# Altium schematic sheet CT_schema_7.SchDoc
size 274 x 160 mm
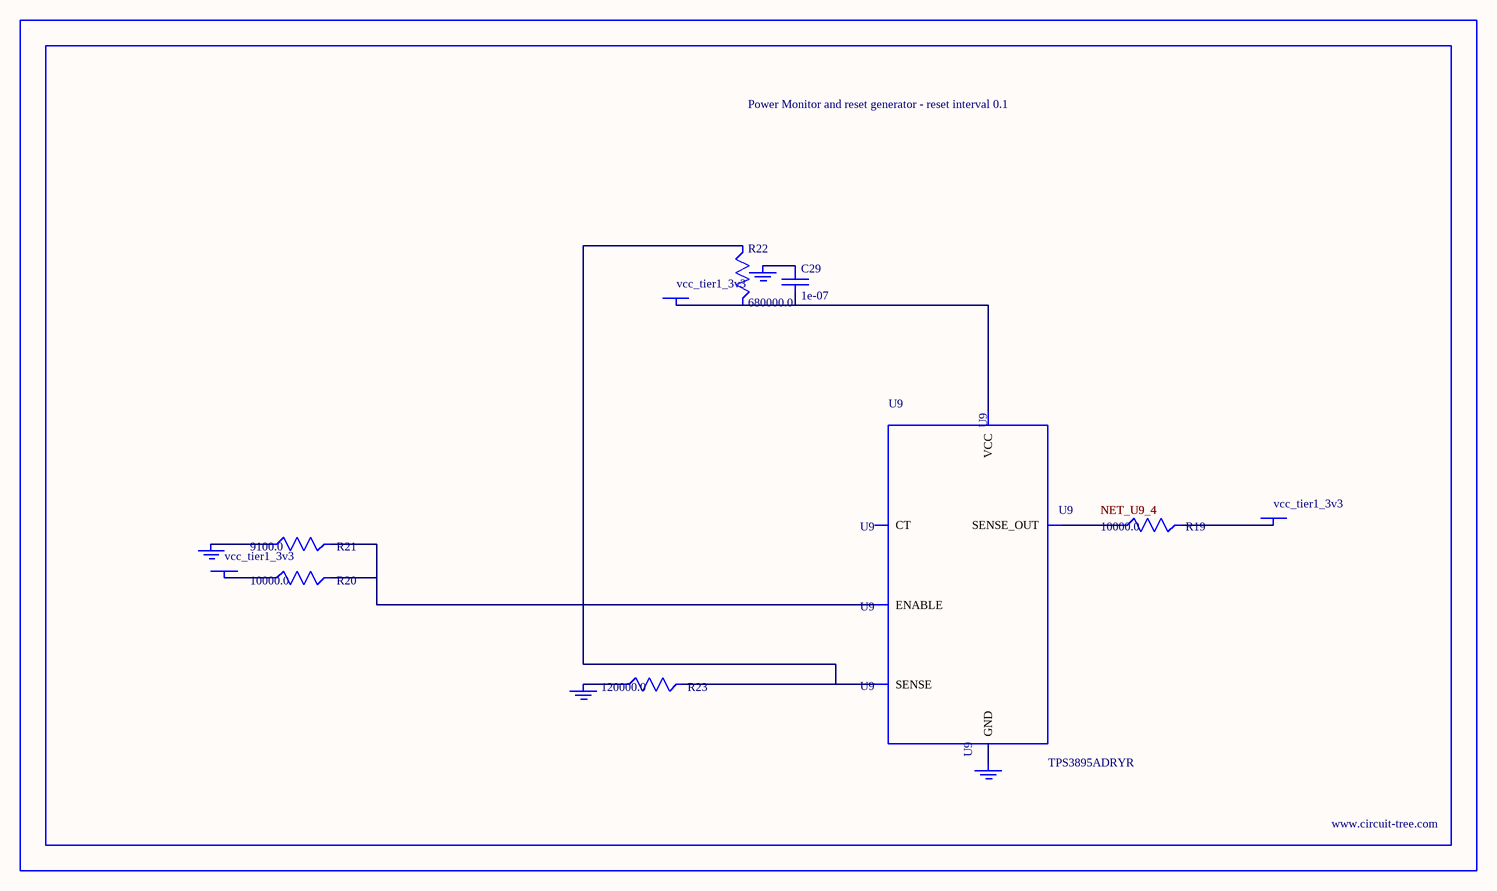
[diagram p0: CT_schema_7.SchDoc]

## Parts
BORDER6  (no value)
C29  1e-07  [C0402]
GND_INSTANCE_6_0  (no value)
GND_INSTANCE_6_1  (no value)
GND_INSTANCE_6_2  (no value)
GND_INSTANCE_6_3  (no value)
POWER_INSTANCE_6_0  vcc_tier1_3v3
POWER_INSTANCE_6_1  vcc_tier1_3v3
POWER_INSTANCE_6_2  vcc_tier1_3v3
R19  10000.0  [R0603]
R20  10000.0  [R0603]
R21  9100.0  [R0603]
R22  680000.0  [R0603]
R23  120000.0  [R0603]
U9  TPS3895ADRYR  [SON-6]

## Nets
NetC29_1: C29.1 GND_INSTANCE_6_2.0(GND)
NetC29_2: C29.2 POWER_INSTANCE_6_2.0(PWR) R22.2 U9.6(VCC)
NetGND_INSTANCE_6_0_0: GND_INSTANCE_6_0.0(GND) R21.1
NetGND_INSTANCE_6_1_0: GND_INSTANCE_6_1.0(GND) R23.1
NetGND_INSTANCE_6_3_0: GND_INSTANCE_6_3.0(GND) U9.2(GND)
NetPOWER_INSTANCE_6_0_0: POWER_INSTANCE_6_0.0(PWR) R20.1
NetPOWER_INSTANCE_6_1_0: POWER_INSTANCE_6_1.0(PWR) R19.2
NetR19_1: R19.1 U9.4(SENSE_OUT)
NetR20_2: R20.2 R21.2 U9.1(ENABLE)
NetR22_1: R22.1 R23.2 U9.3(SENSE)

Not connected (* = marked no-connect by the designer): U9 5(CT)

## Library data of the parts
BORDER6 = BORDER_PAGE6
C29 = C0402C104K3RACTU
GND_INSTANCE_6_0-GND_INSTANCE_6_3 = GND
POWER_INSTANCE_6_0-POWER_INSTANCE_6_2 = PWR
R19 R20 = RC0603JR-0710KL
R21 = RC0603JR-079K1L
R22 = RC0603JR-07680KL
R23 = RC0603JR-07120KL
